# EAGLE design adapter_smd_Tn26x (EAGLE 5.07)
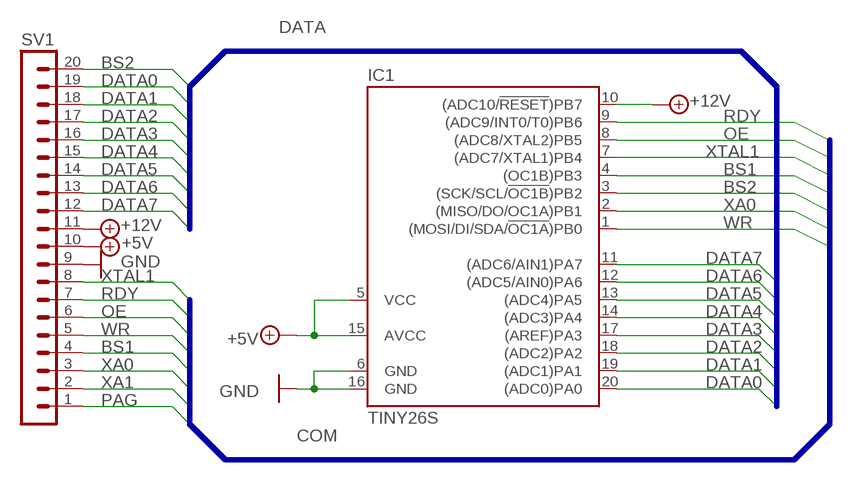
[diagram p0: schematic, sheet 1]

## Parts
IC1  TINY26S  [SO20L]
SV1  MA20-1  [MA20-1]

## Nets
+5V: IC1.5(VCC) IC1.15(AVCC) SV1.10
+12V: IC1.10((ADC10/!RESET!)PB7) SV1.11
BS1: IC1.4((OC1B)PB3) SV1.4
BS2: IC1.3((SCK/SCL/!OC1B!)PB2) SV1.20
DATA0: IC1.20((ADC0)PA0) SV1.19
DATA1: IC1.19((ADC1)PA1) SV1.18
DATA2: IC1.18((ADC2)PA2) SV1.17
DATA3: IC1.17((AREF)PA3) SV1.16
DATA4: IC1.14((ADC3)PA4) SV1.15
DATA5: IC1.13((ADC4)PA5) SV1.14
DATA6: IC1.12((ADC5/AIN0)PA6) SV1.13
DATA7: IC1.11((ADC6/AIN1)PA7) SV1.12
GND: IC1.6(GND) IC1.16(GND) SV1.9
OE: IC1.8((ADC8/XTAL2)PB5) SV1.6
PAG: SV1.1
RDY: IC1.9((ADC9/INT0/T0)PB6) SV1.7
WR: IC1.1((MOSI/DI/SDA/!OC1A!)PB0) SV1.5
XA0: IC1.2((MISO/DO/OC1A)PB1) SV1.3
XA1: SV1.2
XTAL1: IC1.7((ADC7/XTAL1)PB4) SV1.8

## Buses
DATA
COM

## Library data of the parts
IC1 = atmel:TINY26*: 8-bit AVR Microcontroller with 2K Bytes Flash Source: http://www.atmel.com .. doc1477.pdf
SV1 = con-lstb:MA20-1: PIN HEADER

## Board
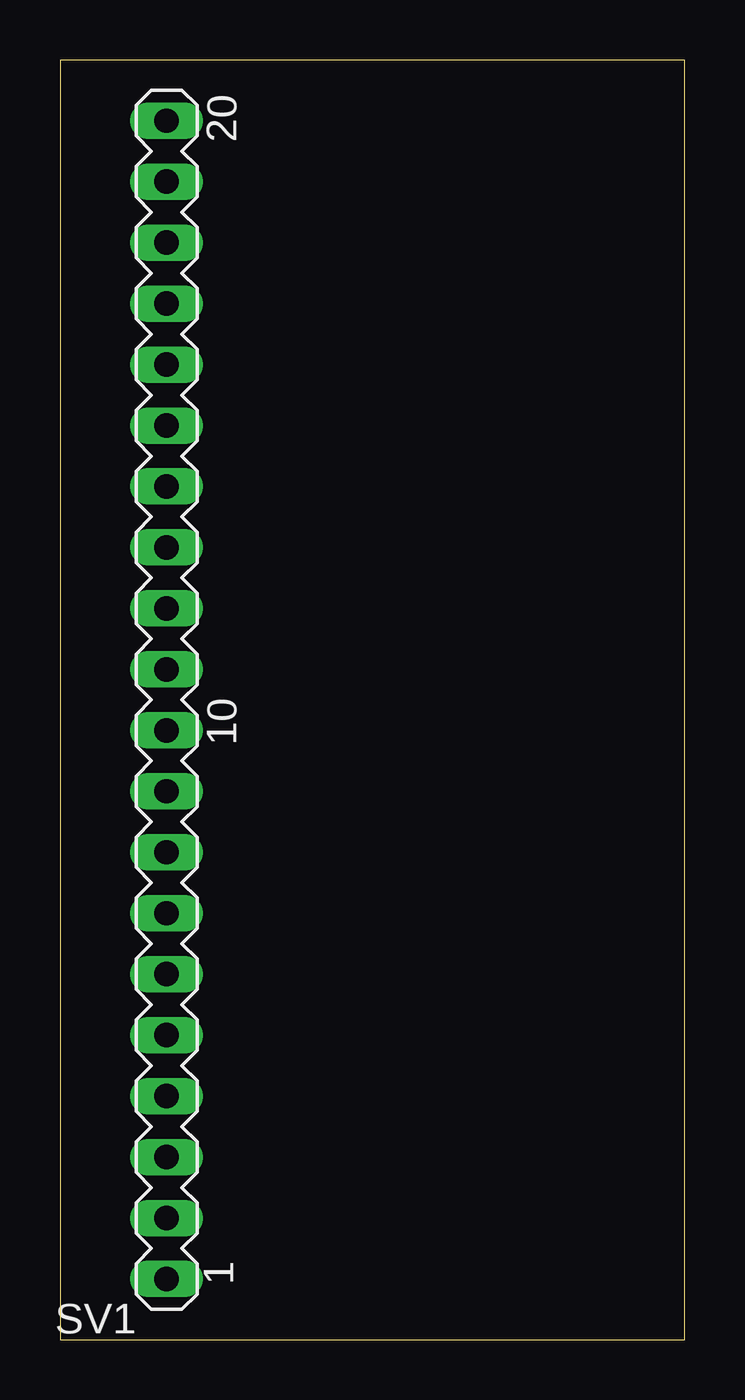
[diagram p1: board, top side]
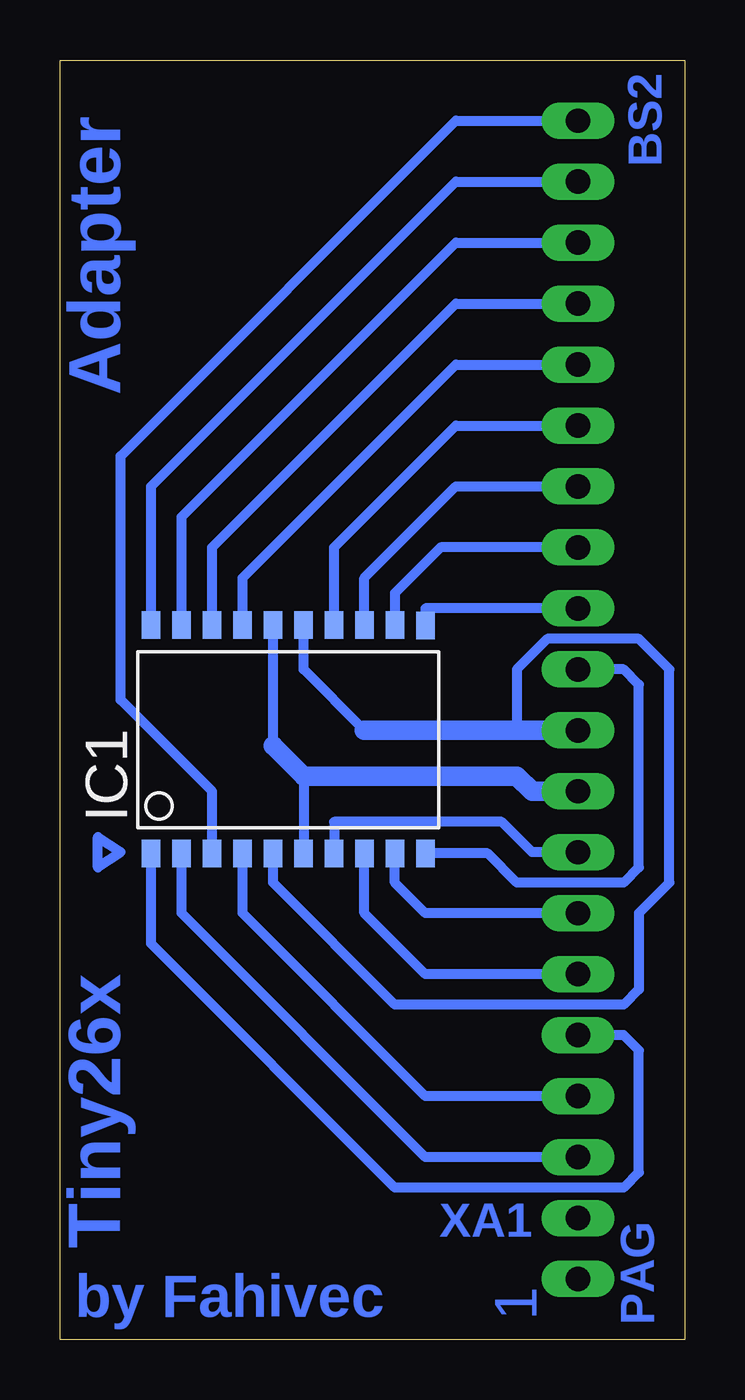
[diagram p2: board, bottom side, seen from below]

Size 26.02 x 53.33 mm. Coordinates in mm from the lower left corner, seen from the top.
Outline: 0,0 26.02,0 26.02,53.33 0,53.33 0,0
Copper layers (1*16): Top 0.035mm / dielectric 1.5mm / Bottom 0.035mm
Design rules "default *": minimum track width 10mil, minimum drill 24mil, track to track 24mil, track to pad 24mil, pad to pad 8mil, via to via 8mil, smd to smd 8mil, copper to edge 8mil, drill to drill 8mil, minimum pad ring 10mil, minimum via ring 8mil, stop-mask expansion 4mil, vias tented up to drill 0mil, thermal gap 10mil

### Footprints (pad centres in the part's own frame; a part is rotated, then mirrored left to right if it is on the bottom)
SO20L = smd 0.762 x 1.143: 1 -5.08,-5.131; 2 -3.81,-5.131; 3 -2.54,-5.131; 4 -1.27,-5.131; 5 0,-5.131; 6 1.27,-5.131; 7 2.54,-5.131; 8 3.81,-5.131; 9 5.08,-5.131; 10 6.35,-5.131; 11 6.35,4.369; 12 5.08,4.394; 13 3.81,4.394; 14 2.54,4.394; 15 1.27,4.394; 16 0,4.394; 17 -1.27,4.394; 18 -2.54,4.394; 19 -3.81,4.394; 20 -5.08,4.394
MA20-1 = drill 1.016 long: 1 -24.13,0; 2 -21.59,0; 3 -19.05,0; 4 -16.51,0; 5 -13.97,0; 6 -11.43,0; 7 -8.89,0; 8 -6.35,0; 9 -3.81,0; 10 -1.27,0; 11 1.27,0; 12 3.81,0; 13 6.35,0; 14 8.89,0; 15 11.43,0; 16 13.97,0; 17 16.51,0; 18 19.05,0; 19 21.59,0; 20 24.13,0

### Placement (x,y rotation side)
IC1  17.14,25.4 0 bottom
SV1  4.45,26.67 90 top

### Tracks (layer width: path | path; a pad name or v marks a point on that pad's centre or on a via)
+5V
  Bottom 0.406: 13.34,25.4 15.88,27.94 IC1.15 | IC1.5 17.14,19.05 12.06,13.97 2.54,13.97 1.91,14.61 1.91,17.78 0.64,19.05 0.64,27.94 1.91,29.21 5.71,29.21 6.99,27.94 6.99,25.4
  Bottom 0.813: SV1.10 6.99,25.4 13.34,25.4
+12V
  Bottom 0.406: IC1.10 8.2,20.27 6.99,19.05 2.54,19.05 1.91,19.68 1.91,27.3 2.54,27.94 SV1.11
BS1
  Bottom 0.406: SV1.4 10.79,10.16 18.41,17.78 IC1.4
BS2
  Bottom 0.406: SV1.20 9.53,50.8 23.49,36.83 23.49,26.67 19.68,22.86 IC1.3
DATA0
  Bottom 0.406: SV1.19 9.53,48.26 22.22,35.56 IC1.20
DATA1
  Bottom 0.406: SV1.18 9.53,45.72 20.95,34.29 IC1.19
DATA2
  Bottom 0.406: SV1.17 9.53,43.18 19.68,33.02 IC1.18
DATA3
  Bottom 0.406: SV1.16 9.53,40.64 18.41,31.75 IC1.17
DATA4
  Bottom 0.406: SV1.15 9.53,38.1 14.61,33.02 IC1.14
DATA5
  Bottom 0.406: SV1.14 9.53,35.56 13.34,31.75 IC1.13
DATA6
  Bottom 0.406: IC1.12 12.06,31.11 10.16,33.02 SV1.13
DATA7
  Bottom 0.406: IC1.11 10.79,30.48 SV1.12
GND
  Bottom 0.406: 15.88,23.5 IC1.6 | 17.14,24.77 IC1.16
  Bottom 0.813: SV1.9 6.35,22.86 6.99,23.5 15.88,23.5 17.14,24.77
N$1
  Bottom 0.406: 24.45,20.95 23.49,20.32 24.45,19.68 24.45,20.95
OE
  Bottom 0.406: SV1.6 10.79,15.24 13.34,17.78 IC1.8
RDY
  Bottom 0.406: SV1.7 10.79,17.78 12.06,19.05 IC1.9
WR
  Bottom 0.406: IC1.1 22.22,16.51 12.06,6.35 2.54,6.35 1.91,6.99 1.91,12.06 2.54,12.7 SV1.5
XA0
  Bottom 0.406: SV1.3 10.79,7.62 20.95,17.78 IC1.2
XTAL1
  Bottom 0.406: SV1.8 6.35,20.32 7.62,21.59 14.61,21.59 IC1.7

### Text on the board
Bottom: BS2 | Adapter | XA1 | Tiny26x | 1 | PAG | by Fahivec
